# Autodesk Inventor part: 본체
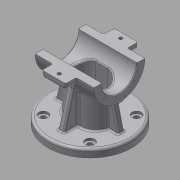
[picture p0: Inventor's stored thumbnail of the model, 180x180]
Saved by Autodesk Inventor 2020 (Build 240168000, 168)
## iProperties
Created: 2015-12
Part Number: 본체
Material: 알루미늄 6061
Document SubType Name: Modeling
Designer: mduedu
Density: 2.71 g/cm^3
Appearance: 알루미늄 - 평지
Mass: 512.605 g
Surface Area: 486.321 cm^2
Volume: 189.153 cm^3
Author: mduedu
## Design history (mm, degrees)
sketch "스케치1"
  geometry: L1 (40, 35)-(-40, 35); L2 (-40, 35)-(-40, -35); L3 (-40, -35)-(40, -35); L4 (40, -35)-(40, 35); L5 (40, 35)-(-40, -35); L6 (-40, 35)-(40, -35); 2 further points
  constraints: 12 end point, 2 midpoint, 2 parallel, 1 coincident, 1 horizontal, 1 perpendicular, 3 other
  dimensions: "d0" = 80 distance of L2.end L3.end; "d2" = 70 distance of L1.end L2.end
extrude "돌출1" new body sketch "스케치1" distance "d3" = 10; taper "d4" = 0 deg
sketch "스케치2"
  geometry: C1 r 32.5 at (75, 0); 1 further point
  constraints: 1 centre point
  dimensions: "d5" = 65 diameter of C1; "d116" = 75 distance of point (0, 0) C1.centre
extrude "돌출2" join sketch "스케치2" stored distance "d7" = 75; taper "d8" = 0 deg
sketch "스케치3"
  geometry: L1 (-27.5, -20)-(27.5, -20); L2 (27.5, -20)-(27.5, 20); L3 (27.5, 20)-(-27.5, 20); L4 (-27.5, 20)-(-27.5, -20); L5 (-27.5, -20)-(27.5, 20); L6 (27.5, -20)-(-27.5, 20); 1 further point
  constraints: 12 end point, 2 midpoint, 2 parallel, 1 horizontal, 1 perpendicular
  dimensions: "d9" = 55 distance of L2.end L3.end; "d11" = 40 distance of L1.end L2.end
extrude "돌출3" new body sketch "스케치3" stored distance "d12" = 75; taper "d13" = 0 deg
fillet "모깎기1"
fillet "모깎기2"
feature "결합1"
  node "솔리드2"
sketch "스케치4"
  geometry: L1 (-37.5, 42.5)-(37.5, 42.5) reference; L2 (32.5, 42.5)-(40.151, 10); L3 (37.5, 42.5)-(37.5, 107.5) reference; L4 (53.151, 0)-(53.151, 10) reference; L5 (53.151, 10)-(-53.151, 10) reference; 1 further point
  constraints: 2 end point, 2 point on line
  dimensions: "d15" = 5 distance from line of L2.start L3; "d117" = 13 distance from line of L2.end L4
sketch "스케치5"
  geometry: L1 (10, 37.151)-(54.507, 25.225); L2 (0, 53.151)-(10, 53.151) reference; L3 (10, -53.151)-(10, 53.151) reference; 2 further points
  constraints: 2 end point, 1 point on line, 2 other
  dimensions: "d118" = 16 distance from line of L1.start L2; "d119" = 75 deg angle of L1 L3
feature "리브1" dims "d19" = 1, "d20" = 8, "d21" = 0, "d22" = 0, "d23" = 1, "d24" = 1
feature "리브2" dims "d25" = 1, "d26" = 8, "d27" = 0, "d28" = 0, "d29" = 1, "d30" = 1
fillet "모깎기4" dims "d31" = 2
fillet "모깎기5" dims "d32" = 2
fillet "모깎기6" dims "d33" = 2
sketch "스케치6"
  geometry: L1 (0, 0)-(-29.698, 29.698); L2 (0, 0)-(-42, 0); A1 r 42 centre (0, 0) between (-29.698, 29.698) and (-42, 0); 5 further points
  constraints: 4 end point, 2 coincident, 2 point on circle, 1 centre point, 1 horizontal, 5 other
  dimensions: "d122" = 45 deg angle of L1 L2; "d126" = 360 deg dimension on point (0, 0) point (-29.698, 29.698) (derived); "d150" = 84 diameter of A1
hole "구멍1" sketch "스케치6" at (-29.698, 29.698), (-29.698, -29.698), (29.698, -29.698), (29.698, 29.698) diameter "d34" = 7; stored, may be unused: countersink angle "d38" = 90 deg, drill point angle "d40" = 118 deg; dims "d35" = 6, "d36" = 12, "d37" = 3, "d39" = 8
fillet "모깎기13" dims "d131" = 3
hole "구멍2" diameter "d44" = 45; stored, may be unused: countersink angle "d48" = 90 deg, drill point angle "d50" = 118 deg; dims "d42" = 10, "d43" = 10, "d45" = 6, "d46" = 4, "d47" = 2, "d49" = 8
sketch "스케치7" dims "d52" = 26.5
  geometry: L1 (0, 0)-(32.5, 0); L2 (0, 0)-(22.981, 22.981); A1 r 32.5 centre (0, 0) between (32.5, 0) and (22.981, 22.981) reference; 3 further points
  constraints: 4 end point, 2 point on circle, 1 coincident, 1 horizontal, 1 point on line, 3 other
  dimensions: "d51" = 45 deg angle of L2 L1
hole "구멍3" sketch "스케치7" at (18.738, 18.738) diameter "d54" = 2.459; stored, may be unused: countersink angle "d58" = 90 deg, drill point angle "d60" = 118 deg; dims "d55" = 8, "d56" = 4, "d57" = 2, "d59" = 10
sketch "스케치8"
  geometry: L1 (67.5, 31.623)-(67.5, 46); L2 (67.5, 46)-(82.5, 46); L3 (82.5, 46)-(82.5, 31.623); A1 r 32.5 centre (75, 0) between (82.5, 31.623) and (67.5, 31.623) reference; 2 further points
  constraints: 6 end point, 2 point on circle, 1 horizontal, 1 midpoint, 1 parallel, 1 vertical, 1 vertical alignment
  dimensions: "d64" = 15 distance of L1.end L2.end; "d66" = 46 distance from line of L2 A1.centre
extrude "돌출4" join sketch "스케치8" stored distance "d67" = 30; taper "d68" = 0 deg
fillet "모깎기8" dims "d69" = 3
fillet "모깎기9" dims "d70" = 2
node "작업 평면2"
sketch "스케치16"
  geometry: L1 (33.166, 67.5)-(44, 67.5) reference; L2 (42.5, 67.5)-(28.53, 59.434); L3 (46, 70.5)-(46, 79.5) reference; 2 further points
  constraints: 2 end point, 1 point on line, 2 other
  dimensions: "d138" = 30 deg angle of L2 L1; "d139" = 3.5 distance from line of L2.start L3
feature "리브3" sketch "스케치16" dims "d140" = 1, "d141" = 3, "d142" = 0, "d143" = 0, "d144" = 1, "d145" = 1
fillet "모깎기14" dims "d146" = 1
fillet "모깎기15" dims "d147" = 1
sketch "스케치9"
  geometry: L1 (-76, 82.5)-(76, 82.5); L2 (76, 82.5)-(76, 0); L3 (76, 0)-(-76, 0); L4 (-76, 0)-(-76, 82.5); L5 (-46, 4.5)-(-46, -4.5) reference; C1 r 32.5 at (0, 0) reference; 2 further points
  constraints: 8 end point, 2 parallel, 1 coincident, 1 horizontal, 1 midpoint, 1 perpendicular
  dimensions: "d71" = 50 distance edge to line of C1 L1; "d72" = 30 distance between parallel lines of L4 L5
extrude "돌출5" cut sketch "스케치9" extent not by distance; stored distance "d73" = 0; taper "d74" = 0 deg
node "작업 평면1"
sketch "스케치10"
  geometry: L1 (-7.5, 15)-(7.5, 15); L2 (-7.5, -15)-(7.5, -15); A1 r 20 centre (-7.5, 0) between (-7.5, 20) and (-26.742, 5.455) reference; A2 r 20 centre (7.5, 0) between (26.742, 5.455) and (7.5, 20) reference; A3 r 15 centre (-7.5, 0) between (-7.5, 15) and (-7.5, -15); A4 r 15 centre (7.5, 0) between (7.5, -15) and (7.5, 15); 1 further point
  constraints: 7 point on circle, 4 end point, 4 tangent, 3 point on line, 2 centre point, 2 coincident, 1 horizontal
  dimensions: "d77" = 5 radial gap between concentric circles of A3 A1
extrude "돌출6" cut sketch "스케치10" extent not by distance; stored distance "d78" = 50; taper "d79" = 0 deg
fillet "모깎기10" dims "d80" = 3
sketch "스케치11"
  geometry: 2 further points
  constraints: 1 coincident
hole "구멍4" sketch "스케치11" at (0, 0) diameter "d81" = 12; stored, may be unused: countersink angle "d85" = 90 deg, drill point angle "d87" = 118 deg; dims "d82" = 8, "d83" = 40, "d84" = 10, "d86" = 10
sketch "스케치12"
  geometry: C1 r 10 at (0, 0); 1 further point
  constraints: 1 centre point, 1 coincident
  dimensions: "d88" = 20 diameter of C1
extrude "돌출7" cut sketch "스케치12" distance "d89" = 5; taper "d90" = 0 deg
chamfer "모따기1" distance "d91" = 1; stored, may be unused: second distance "d92" = 2, angle "d93" = 45 deg
fillet "모깎기11" dims "d94" = 0.5
sketch "스케치13"
  geometry: L1 (-3, 10.834)-(-3, 1.039) reference; L2 (27, 1.039)-(27, 10.834) reference; L3 (-3, 5.936)-(27, 5.936); L4 (24, 12.834)-(0, 12.834) reference; L5 (12, 12.834)-(12, -33.166); 1 further point
  constraints: 4 end point, 4 midpoint, 1 perpendicular, 1 point on line
hole "구멍5" sketch "스케치13" at (12, 5.936) diameter "d101" = 4.5; stored, may be unused: countersink angle "d105" = 90 deg, drill point angle "d107" = 0 deg; dims "d102" = 6, "d103" = 4, "d104" = 2, "d106" = 8
fillet "모깎기12" dims "d115" = 0.3
fillet "모깎기16" dims "d155" = 0.5
chamfer "모따기2" distance "d157" = 1; stored, may be unused: second distance "d158" = 2, angle "d159" = 45 deg
node "솔리드1"
mirror "대칭1"
mirror "대칭2"
pattern_circular "원형 패턴1" dims angle "d62" = 360 deg
mirror "대칭3"
mirror "대칭7"
mirror "대칭4"
mirror "대칭6"
other parameters: "d137" = -5
